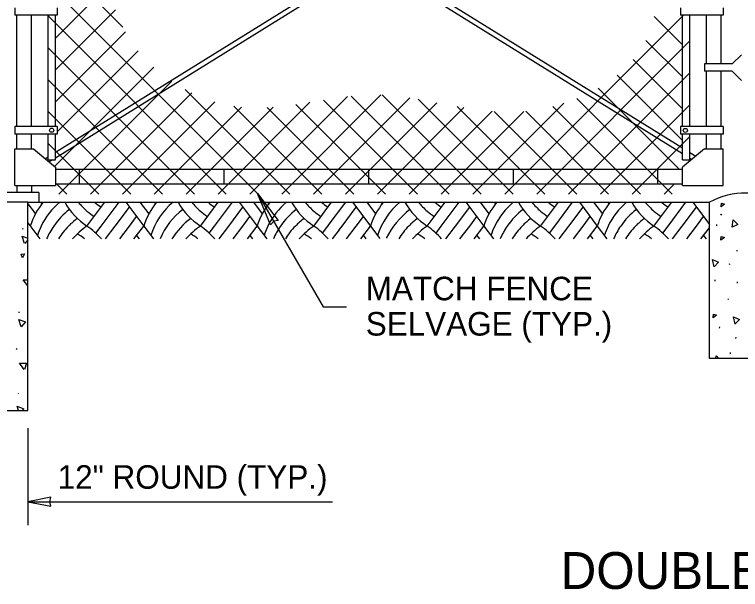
# Model space of a CAD drawing. Extents: x 99862 to 104211, y 98939 to 105076.
# Drawn here: x 101012 to 101505.8, y 101016.7 to 101407.7 of the extents above; entities that cross this region are included whole.
import ezdxf

# ---------------------------------------------------------------- set-up
doc = ezdxf.new("R2010")
doc.units = 0
for name, color, linetype in [('Level 10', 7, 'Continuous'), ('Level 15', 7, 'Continuous'), ('Level 20', 7, 'Continuous'), ('Level 4', 7, 'Continuous'), ('Level 6', 7, 'Continuous'), ('Level 7', 7, 'Continuous')]:
    doc.layers.add(name, color=color, linetype=linetype)

msp = doc.modelspace()

# ---------------------------------------------------------------- linework, layer by layer
at = {"layer": 'Level 10'}
for p, q in [((101021.02, 101280.06), (101484.66, 101280.06)), ((101021.03, 101278.93), (101026.17, 101272.08)), ((101029.82, 101280.06), (101030.64, 101278.97)), ((101061.26, 101263.86), (101073.42, 101280.06)), ((101070.9, 101263.86), (101083.06, 101280.06)), ((101087.67, 101280.06), (101099.83, 101263.86)), ((101097.31, 101280.06), (101103.3, 101272.08)), ((101106.95, 101280.06), (101107.77, 101278.97)), ((101138.39, 101263.86), (101150.55, 101280.06)), ((101148.04, 101263.86), (101160.19, 101280.06)), ((101164.8, 101280.06), (101176.96, 101263.86)), ((101174.45, 101280.06), (101180.43, 101272.08)), ((101184.09, 101280.06), (101184.91, 101278.97)), ((101221.39, 101271.68), (101227.68, 101280.06)), ((101225.38, 101264.14), (101237.33, 101280.06)), ((101241.94, 101280.06), (101260.51, 101255.3)), ((101251.58, 101280.06), (101257.57, 101272.08)), ((101261.22, 101280.06), (101262.04, 101278.97)), ((101292.66, 101263.86), (101304.82, 101280.06)), ((101302.3, 101263.86), (101314.46, 101280.06)), ((101319.07, 101280.06), (101331.23, 101263.86)), ((101328.71, 101280.06), (101334.7, 101272.08)), ((101338.36, 101280.06), (101339.17, 101278.97)), ((101369.79, 101263.86), (101381.95, 101280.06)), ((101379.44, 101263.86), (101391.59, 101280.06)), ((101396.21, 101280.06), (101408.36, 101263.86)), ((101405.85, 101280.06), (101411.83, 101272.08)), ((101415.49, 101280.06), (101416.31, 101278.97)), ((101446.93, 101263.86), (101459.08, 101280.06)), ((101456.57, 101263.86), (101468.73, 101280.06)), ((101473.34, 101280.06), (101484.66, 101264.97)), ((101080.54, 101263.86), (101090.19, 101276.71)), ((101157.68, 101263.86), (101167.32, 101276.71)), ((101234.81, 101263.86), (101244.45, 101276.71)), ((101311.94, 101263.86), (101321.59, 101276.71)), ((101389.08, 101263.86), (101398.72, 101276.71)), ((101466.21, 101263.86), (101475.85, 101276.71)), ((101090.19, 101263.86), (101095.01, 101270.28)), ((101167.32, 101263.86), (101172.14, 101270.28)), ((101215.53, 101263.86), (101221.49, 101271.8)), ((101244.45, 101263.86), (101249.27, 101270.28)), ((101321.59, 101263.86), (101326.41, 101270.28)), ((101398.72, 101263.86), (101403.54, 101270.28)), ((101475.85, 101263.86), (101480.67, 101270.28)), ((101020.99, 101266.13), (101029.28, 101255.07)), ((101067.3, 101259.06), (101070.9, 101263.86)), ((101073.96, 101255.07), (101080.54, 101263.86)), ((101083.6, 101255.07), (101090.19, 101263.86)), ((101093.24, 101255.07), (101099.83, 101263.86)), ((101099.83, 101263.86), (101106.42, 101255.07)), ((101144.44, 101259.06), (101148.04, 101263.86)), ((101151.09, 101255.07), (101157.68, 101263.86)), ((101160.73, 101255.07), (101167.32, 101263.86)), ((101170.37, 101255.07), (101176.96, 101263.86)), ((101176.96, 101263.86), (101183.55, 101255.07)), ((101221.57, 101259.06), (101225.17, 101263.86)), ((101225.17, 101263.86), (101225.45, 101264.22)), ((101232.83, 101261.22), (101234.81, 101263.86)), ((101237.86, 101255.07), (101244.45, 101263.86)), ((101247.51, 101255.07), (101254.09, 101263.86)), ((101298.7, 101259.06), (101302.3, 101263.86)), ((101305.36, 101255.07), (101311.94, 101263.86)), ((101315, 101255.07), (101321.59, 101263.86)), ((101324.64, 101255.07), (101331.23, 101263.86)), ((101331.23, 101263.86), (101337.82, 101255.07)), ((101375.84, 101259.06), (101379.44, 101263.86)), ((101382.49, 101255.07), (101389.08, 101263.86)), ((101392.13, 101255.07), (101398.72, 101263.86)), ((101401.77, 101255.07), (101408.36, 101263.86)), ((101408.36, 101263.86), (101414.95, 101255.07)), ((101452.97, 101259.06), (101456.57, 101263.86)), ((101459.62, 101255.07), (101466.21, 101263.86)), ((101469.27, 101255.07), (101475.85, 101263.86)), ((101228.22, 101255.07), (101232.97, 101261.39)), ((101478.91, 101255.07), (101484.66, 101262.74)), ((101095.01, 101257.43), (101096.77, 101255.07)), ((101172.14, 101257.43), (101173.91, 101255.07)), ((101249.27, 101257.43), (101251.04, 101255.07)), ((101326.41, 101257.43), (101328.17, 101255.07)), ((101403.54, 101257.43), (101405.31, 101255.07)), ((101480.67, 101257.43), (101482.44, 101255.07))]:
    msp.add_line(p, q, dxfattribs=at)
for centre, radius, start, end in [((101069.2, 101249.06), 48.8, 140.5627, 162.3605), ((101074.02, 101242.64), 48.8, 129.9188, 154.2266), ((101088.48, 101304.36), 48.8, 209.8569, 236.0964), ((101093.3, 101310.79), 48.8, 219.0175, 228.9599), ((101098.12, 101317.21), 48.8, 229.5771, 236.0964), ((101146.33, 101249.06), 48.8, 140.5627, 162.3566), ((101151.15, 101242.64), 48.8, 129.9188, 162.3566), ((101165.61, 101304.36), 48.8, 209.8569, 236.0964), ((101170.44, 101310.79), 48.8, 219.0175, 228.9599), ((101175.26, 101317.21), 48.8, 229.5771, 236.0964), ((101223.46, 101249.06), 48.8, 140.5627, 162.3566), ((101228.29, 101242.64), 48.8, 129.9188, 154.2266), ((101242.75, 101304.36), 48.8, 209.8569, 236.0964), ((101247.57, 101310.79), 48.8, 219.0175, 228.9599), ((101252.39, 101317.21), 48.8, 229.5771, 236.0964), ((101300.6, 101249.06), 48.8, 140.5627, 162.3566), ((101305.42, 101242.64), 48.8, 129.9188, 162.3566), ((101319.88, 101304.36), 48.8, 209.8569, 236.0964), ((101324.7, 101310.79), 48.8, 219.0175, 228.9599), ((101329.52, 101317.21), 48.8, 229.5771, 236.0964), ((101377.73, 101249.06), 48.8, 140.5627, 162.3566), ((101382.55, 101242.64), 48.8, 129.9188, 154.2266), ((101397.02, 101304.36), 48.8, 209.8569, 236.0964), ((101401.84, 101310.79), 48.8, 219.0175, 228.9599), ((101406.66, 101317.21), 48.8, 229.5771, 236.0964), ((101454.87, 101249.06), 48.8, 140.5627, 162.3566), ((101459.69, 101242.64), 48.8, 129.9188, 154.2266), ((101474.15, 101304.36), 48.8, 209.8569, 236.0964), ((101478.97, 101310.79), 48.8, 219.0175, 228.9599), ((101483.79, 101317.21), 48.8, 229.5771, 236.0964), ((101078.84, 101236.21), 48.8, 127.1006, 145.4911), ((101093.3, 101310.79), 48.8, 228.9599, 236.0964), ((101155.97, 101236.21), 48.8, 127.1006, 157.1246), ((101170.43, 101310.79), 48.8, 228.9599, 236.0964), ((101233.11, 101236.21), 48.8, 127.1006, 145.4911), ((101247.57, 101310.79), 48.8, 228.9599, 236.0964), ((101321.85, 101224.91), 64.86, 129.2593, 151.724), ((101324.7, 101310.79), 48.8, 228.9599, 236.0964), ((101387.37, 101236.21), 48.8, 127.1006, 145.4911), ((101401.84, 101310.79), 48.8, 228.9599, 236.0964), ((101464.51, 101236.21), 48.8, 127.1006, 145.4911), ((101478.97, 101310.79), 48.8, 228.9599, 236.0964), ((101083.66, 101229.78), 48.8, 126.331, 135.7128), ((101160.79, 101229.78), 48.8, 126.331, 148.7846), ((101237.93, 101229.78), 48.8, 126.331, 135.7128), ((101315.06, 101229.78), 48.8, 126.331, 135.7128), ((101392.19, 101229.78), 48.8, 126.331, 135.7128), ((101469.33, 101229.78), 48.8, 126.331, 135.7128), ((101074.02, 101242.64), 48.8, 154.2265, 162.3566), ((101078.84, 101236.21), 48.8, 145.491, 157.2609), ((101083.66, 101229.78), 48.8, 135.7127, 148.7846), ((101088.48, 101223.35), 48.8, 123.9036, 139.4601), ((101034.04, 101223.35), 48.8, 40.5399, 56.0963), ((101165.61, 101223.35), 48.8, 123.9036, 139.4601), ((101111.17, 101223.35), 48.8, 40.5399, 56.0963), ((101228.29, 101242.64), 48.8, 154.2265, 162.3566), ((101233.11, 101236.21), 48.8, 145.491, 157.2609), ((101237.93, 101229.78), 48.8, 135.7127, 148.7846), ((101242.75, 101223.35), 48.8, 123.9036, 139.4601), ((101188.31, 101223.35), 48.8, 40.5399, 56.0963), ((101315.06, 101229.78), 48.8, 135.7127, 148.7846), ((101319.88, 101223.35), 48.8, 123.9036, 139.4601), ((101265.44, 101223.35), 48.8, 40.5399, 56.0963), ((101382.55, 101242.64), 48.8, 154.2265, 162.3566), ((101387.37, 101236.21), 48.8, 145.491, 157.2609), ((101392.19, 101229.78), 48.8, 135.7127, 148.7846), ((101397.02, 101223.35), 48.8, 123.9036, 139.4601), ((101342.57, 101223.35), 48.8, 40.5399, 56.0963), ((101459.69, 101242.64), 48.8, 154.2265, 162.3566), ((101464.51, 101236.21), 48.8, 145.491, 157.2609), ((101469.33, 101229.78), 48.8, 135.7127, 148.7846), ((101474.15, 101223.35), 48.8, 123.9036, 139.4601), ((101419.71, 101223.35), 48.8, 40.5399, 56.0963), ((101029.22, 101216.93), 48.8, 51.4164, 58.5465), ((101106.35, 101216.93), 48.8, 51.4164, 58.5465), ((101183.49, 101216.93), 48.8, 51.4164, 58.5465), ((101260.62, 101216.93), 48.8, 51.4164, 58.5465), ((101337.75, 101216.93), 48.8, 51.4164, 58.5465), ((101414.89, 101216.93), 48.8, 51.4164, 58.5465)]:
    msp.add_arc(centre, radius, start, end, dxfattribs=at)
at = {"layer": 'Level 15'}
for p, q in [((101177.37, 101285.94), (101221.84, 101208.92)), ((101221.84, 101208.92), (101237.84, 101208.92)), ((101021.02, 101126.38), (101021.02, 101060.38)), ((101021.02, 101076.38), (101037.02, 101076.38)), ((101037.02, 101076.38), (101228.33, 101076.38))]:
    msp.add_line(p, q, dxfattribs=at)
for points in [[(101177.37, 101285.94), (101191.37, 101267.66), (101188.26, 101267.08), (101186.2, 101264.68)], [(101021.02, 101076.38), (101036.74, 101073.29), (101036.01, 101076.38), (101036.74, 101079.46)]]:
    msp.add_lwpolyline(points, close=True, dxfattribs=at)
at = {"layer": 'Level 4'}
for p, q in [((101034.81, 101450.09), (101085.7, 101399.21)), ((101034.81, 101428.42), (101177.69, 101285.54)), ((101039.83, 101391.67), (101076.24, 101428.09)), ((101034.81, 101406.75), (101156.02, 101285.54)), ((101039.83, 101370), (101080.71, 101410.88)), ((101345.48, 101285.54), (101467.15, 101407.21)), ((101446.98, 101406.36), (101466.35, 101386.99)), ((101039.83, 101348.32), (101087.45, 101395.95)), ((101367.16, 101285.54), (101471.37, 101389.75)), ((101441.52, 101390.16), (101466.35, 101365.32)), ((101034.81, 101385.08), (101134.34, 101285.54)), ((101041.08, 101327.91), (101096.18, 101383)), ((101432.88, 101377.12), (101466.35, 101343.65)), ((101039.23, 101304.38), (101106.72, 101371.87)), ((101388.83, 101285.54), (101471.37, 101368.08)), ((101034.81, 101363.4), (101112.67, 101285.54)), ((101042.06, 101285.54), (101118.88, 101362.36)), ((101421.87, 101366.46), (101466.35, 101321.97)), ((101409, 101357.65), (101464.02, 101302.63)), ((101063.73, 101285.54), (101132.66, 101354.46)), ((101128.13, 101356.78), (101199.36, 101285.54)), ((101193.77, 101285.54), (101261.25, 101353.02)), ((101241.04, 101352.23), (101307.73, 101285.54)), ((101261.95, 101352.99), (101329.4, 101285.54)), ((101085.41, 101285.54), (101148.26, 101348.4)), ((101150.43, 101285.54), (101212.93, 101348.04)), ((101172.1, 101285.54), (101238.49, 101351.93)), ((101215.45, 101285.54), (101280.94, 101351.03)), ((101222.05, 101349.55), (101286.06, 101285.54)), ((101237.12, 101285.54), (101299.35, 101347.77)), ((101286.48, 101350.14), (101351.07, 101285.54)), ((101323.81, 101285.54), (101385.59, 101347.32)), ((101394.43, 101350.55), (101459.44, 101285.54)), ((101107.08, 101285.54), (101166.32, 101344.78)), ((101128.75, 101285.54), (101187.95, 101344.74)), ((101161.13, 101345.44), (101221.04, 101285.54)), ((101183.78, 101344.47), (101242.71, 101285.54)), ((101203.38, 101346.55), (101264.38, 101285.54)), ((101258.79, 101285.54), (101317.63, 101344.38)), ((101313.12, 101345.17), (101372.75, 101285.54)), ((101378.13, 101345.17), (101437.77, 101285.54)), ((101410.5, 101285.54), (101471.37, 101346.41)), ((101034.81, 101341.73), (101091, 101285.54)), ((101280.46, 101285.54), (101336.81, 101341.89)), ((101302.14, 101285.54), (101358.42, 101341.82)), ((101338.17, 101341.79), (101394.42, 101285.54)), ((101359.7, 101341.93), (101416.09, 101285.54)), ((101432.18, 101285.54), (101471.37, 101324.73)), ((101034.81, 101320.06), (101069.32, 101285.54)), ((101056.28, 101292.59), (101056.28, 101302.62)), ((101154.63, 101292.59), (101154.63, 101302.62)), ((101252.98, 101292.59), (101252.98, 101302.62)), ((101351.33, 101292.59), (101351.33, 101302.62)), ((101449.68, 101292.59), (101449.68, 101302.62)), ((101040.59, 101292.6), (101047.65, 101285.54)), ((101453.85, 101285.54), (101460.91, 101292.6))]:
    msp.add_line(p, q, dxfattribs=at)
at = {"layer": 'Level 6'}
for p, q in [((101021.02, 101280.06), (100970.86, 101280.06)), ((101021.02, 101138.38), (101021.02, 101280.06)), ((101484.66, 101173.8), (101484.66, 101280.06)), ((101492.3, 101271.94), (101492.82, 101271.56)), ((101492.7, 101271.87), (101493.22, 101271.49)), ((101489.63, 101263.96), (101489.69, 101264.83)), ((101017.1, 101262.09), (101017.76, 101261.96)), ((101503.47, 101246.7), (101503.53, 101247.57)), ((101498.03, 101238.47), (101498.39, 101237.75)), ((101488.55, 101226.43), (101488.61, 101227.3)), ((101503.81, 101224.98), (101503.87, 101225.85)), ((101484.74, 101215.86), (101484.8, 101216.74)), ((101497.11, 101214.32), (101497.63, 101213.94)), ((101014.7, 101205.38), (101015.36, 101205.24)), ((101491.62, 101194.37), (101491.68, 101195.24)), ((101502.73, 101187.45), (101502.79, 101188.32)), ((101013.14, 101180.67), (101013.79, 101180.14)), ((101498.92, 101176.88), (101498.98, 101177.76)), ((101534.81, 101173.8), (101484.66, 101173.8)), ((101014.75, 101149.72), (101014.64, 101150.02)), ((100970.86, 101138.38), (101021.02, 101138.38))]:
    msp.add_line(p, q, dxfattribs=at)
for points in [[(101492.64, 101276.98), (101492.88, 101279.43), (101495.01, 101278.78), (101492.64, 101276.98)], [(101500.08, 101263.04), (101500.78, 101268.12), (101503.96, 101264.83), (101500.16, 101263.07)], [(101018.85, 101251.97), (101017.28, 101257.09), (101020.93, 101255.69)], [(101020.93, 101254.42), (101018.92, 101252.03)], [(101492.47, 101254.32), (101492.72, 101256.77), (101494.84, 101256.13), (101492.47, 101254.32)], [(101017.38, 101242.23), (101016.52, 101244.65), (101018.82, 101244.98), (101017.38, 101242.23)], [(101487.89, 101236.18), (101486.82, 101241.19), (101490.93, 101239.19), (101487.96, 101236.23)], [(101020.93, 101223.19), (101017.82, 101227.29), (101020.93, 101227.24)], [(101016.45, 101195.25), (101014.88, 101200.37), (101019.34, 101198.66), (101016.52, 101195.32)], [(101487.15, 101201.48), (101487.4, 101203.94), (101489.52, 101203.29), (101487.15, 101201.48)], [(101502.08, 101197.2), (101501.01, 101202.21), (101505.12, 101200.21), (101502.15, 101197.25)], [(101488.93, 101173.8), (101489.18, 101175.61), (101490.93, 101173.8)], [(101018.65, 101166.31), (101015.42, 101170.58), (101020.2, 101170.5), (101018.69, 101166.39)], [(101014.75, 101138.38), (101013.84, 101141.32), (101018.3, 101139.61), (101017.26, 101138.38)]]:
    msp.add_lwpolyline(points, dxfattribs=at)
msp.add_arc((101509.74, 101233.04), 53.29, 61.9275, 118.0725, dxfattribs=at)
at = {"layer": 'Level 7'}
for p, q in [((101466.35, 101578.6), (101039.83, 101313.9)), ((101466.35, 101574.81), (101039.83, 101310.11)), ((101255.6, 101444.02), (101466.35, 101313.23)), ((101258.65, 101445.91), (101466.35, 101317.02)), ((101012.24, 101412.22), (101012.24, 101407.21)), ((101041.08, 101412.22), (101041.08, 101407.21)), ((101465.1, 101412.22), (101465.1, 101407.21)), ((101493.94, 101412.22), (101493.94, 101407.21)), ((101041.08, 101407.21), (101012.24, 101407.21)), ((101013.49, 101331.47), (101013.49, 101407.21)), ((101023.53, 101331.47), (101023.53, 101407.21)), ((101034.81, 101331.47), (101034.81, 101407.21)), ((101039.83, 101331.47), (101039.83, 101407.21)), ((101493.94, 101407.21), (101465.1, 101407.21)), ((101466.35, 101331.47), (101466.35, 101407.21)), ((101471.37, 101331.47), (101471.37, 101407.21)), ((101482.65, 101374.1), (101482.65, 101407.21)), ((101492.68, 101374.1), (101492.68, 101407.21)), ((101506.48, 101380.37), (101500.21, 101374.1)), ((101500.21, 101374.1), (101481.4, 101374.1)), ((101481.4, 101374.1), (101481.4, 101369.09)), ((101500.21, 101369.09), (101481.4, 101369.09)), ((101482.65, 101331.47), (101482.65, 101369.09)), ((101492.68, 101331.47), (101492.68, 101369.09)), ((101506.48, 101362.82), (101500.21, 101369.09)), ((101041.08, 101331.47), (101012.24, 101331.47)), ((101012.24, 101331.47), (101012.24, 101326.46)), ((101041.08, 101331.47), (101041.08, 101326.46)), ((101493.94, 101331.47), (101465.1, 101331.47)), ((101465.1, 101331.47), (101465.1, 101326.46)), ((101493.94, 101331.47), (101493.94, 101326.46)), ((101041.08, 101326.46), (101012.24, 101326.46)), ((101013.49, 101316.43), (101013.49, 101326.46)), ((101023.53, 101316.43), (101023.53, 101326.46)), ((101034.81, 101308.9), (101034.81, 101326.46)), ((101039.83, 101308.9), (101039.83, 101326.46)), ((101493.94, 101326.46), (101465.1, 101326.46)), ((101466.35, 101308.9), (101466.35, 101326.46)), ((101471.37, 101308.9), (101471.37, 101326.46)), ((101482.65, 101316.43), (101482.65, 101326.46)), ((101492.68, 101316.43), (101492.68, 101326.46)), ((101012.24, 101291.35), (101012.24, 101316.43)), ((101012.24, 101316.43), (101024.78, 101316.43)), ((101024.78, 101316.43), (101039.83, 101303.89)), ((101481.4, 101316.43), (101466.35, 101303.89)), ((101471.37, 101313.9), (101475.38, 101311.41)), ((101481.4, 101316.43), (101493.94, 101316.43)), ((101493.94, 101291.35), (101493.94, 101316.43)), ((101034.81, 101310.79), (101032.94, 101309.63)), ((101034.81, 101308.9), (101039.83, 101308.9)), ((101037.88, 101308.9), (101035.54, 101307.46)), ((101466.35, 101308.9), (101471.37, 101308.9)), ((101471.37, 101310.11), (101472.77, 101309.24)), ((101039.83, 101303.89), (101039.83, 101291.35)), ((101466.35, 101291.35), (101466.35, 101303.89)), ((101039.83, 101302.63), (101466.35, 101302.63)), ((101012.24, 101291.35), (101039.83, 101291.35)), ((101013.49, 101291.35), (101013.49, 101286.58)), ((101023.53, 101291.35), (101023.53, 101286.58)), ((101039.83, 101292.6), (101466.35, 101292.6)), ((101466.35, 101291.35), (101493.94, 101291.35)), ((101028.54, 101286.58), (100978.39, 101286.58)), ((101028.54, 101286.58), (101028.54, 101280.06))]:
    msp.add_line(p, q, dxfattribs=at)
for centre in [(101037.29, 101329.02), (101468.27, 101328.9)]:
    msp.add_circle(centre, 1.41, dxfattribs=at)

# ---------------------------------------------------------------- texts
at = {"layer": 'Level 20'}
for s, height, p in [('MATCH FENCE', 16, (101250.88, 101213.38)), ('SELVAGE (TYP.)', 16, (101250.88, 101189.38)), ('12" ROUND (TYP.)', 16, (101041.34, 101085.21)), ('DOUBLE GATE', 25.08, (101383.48, 101017.06))]:
    msp.add_text(s, height=height, dxfattribs=at).set_placement(p)

doc.saveas('drawing.dxf')
